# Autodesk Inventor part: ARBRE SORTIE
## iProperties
Created: 2004-11
Part Number: ARBRE SORTIE
Document SubType Name: Modeling
Designer: Bruno
Manufacturer: Standard
Standards Organization: Custom
Author: Bruno
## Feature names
1. Base1
